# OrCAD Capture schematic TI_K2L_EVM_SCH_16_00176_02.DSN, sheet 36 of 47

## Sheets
36 PAGE45 : K2L_POWER SECTION 4: size C; title: K2L CVVD, CVVD1, bypass caps, K2L 1v8, K2L 1v0 PLL, caps, filters
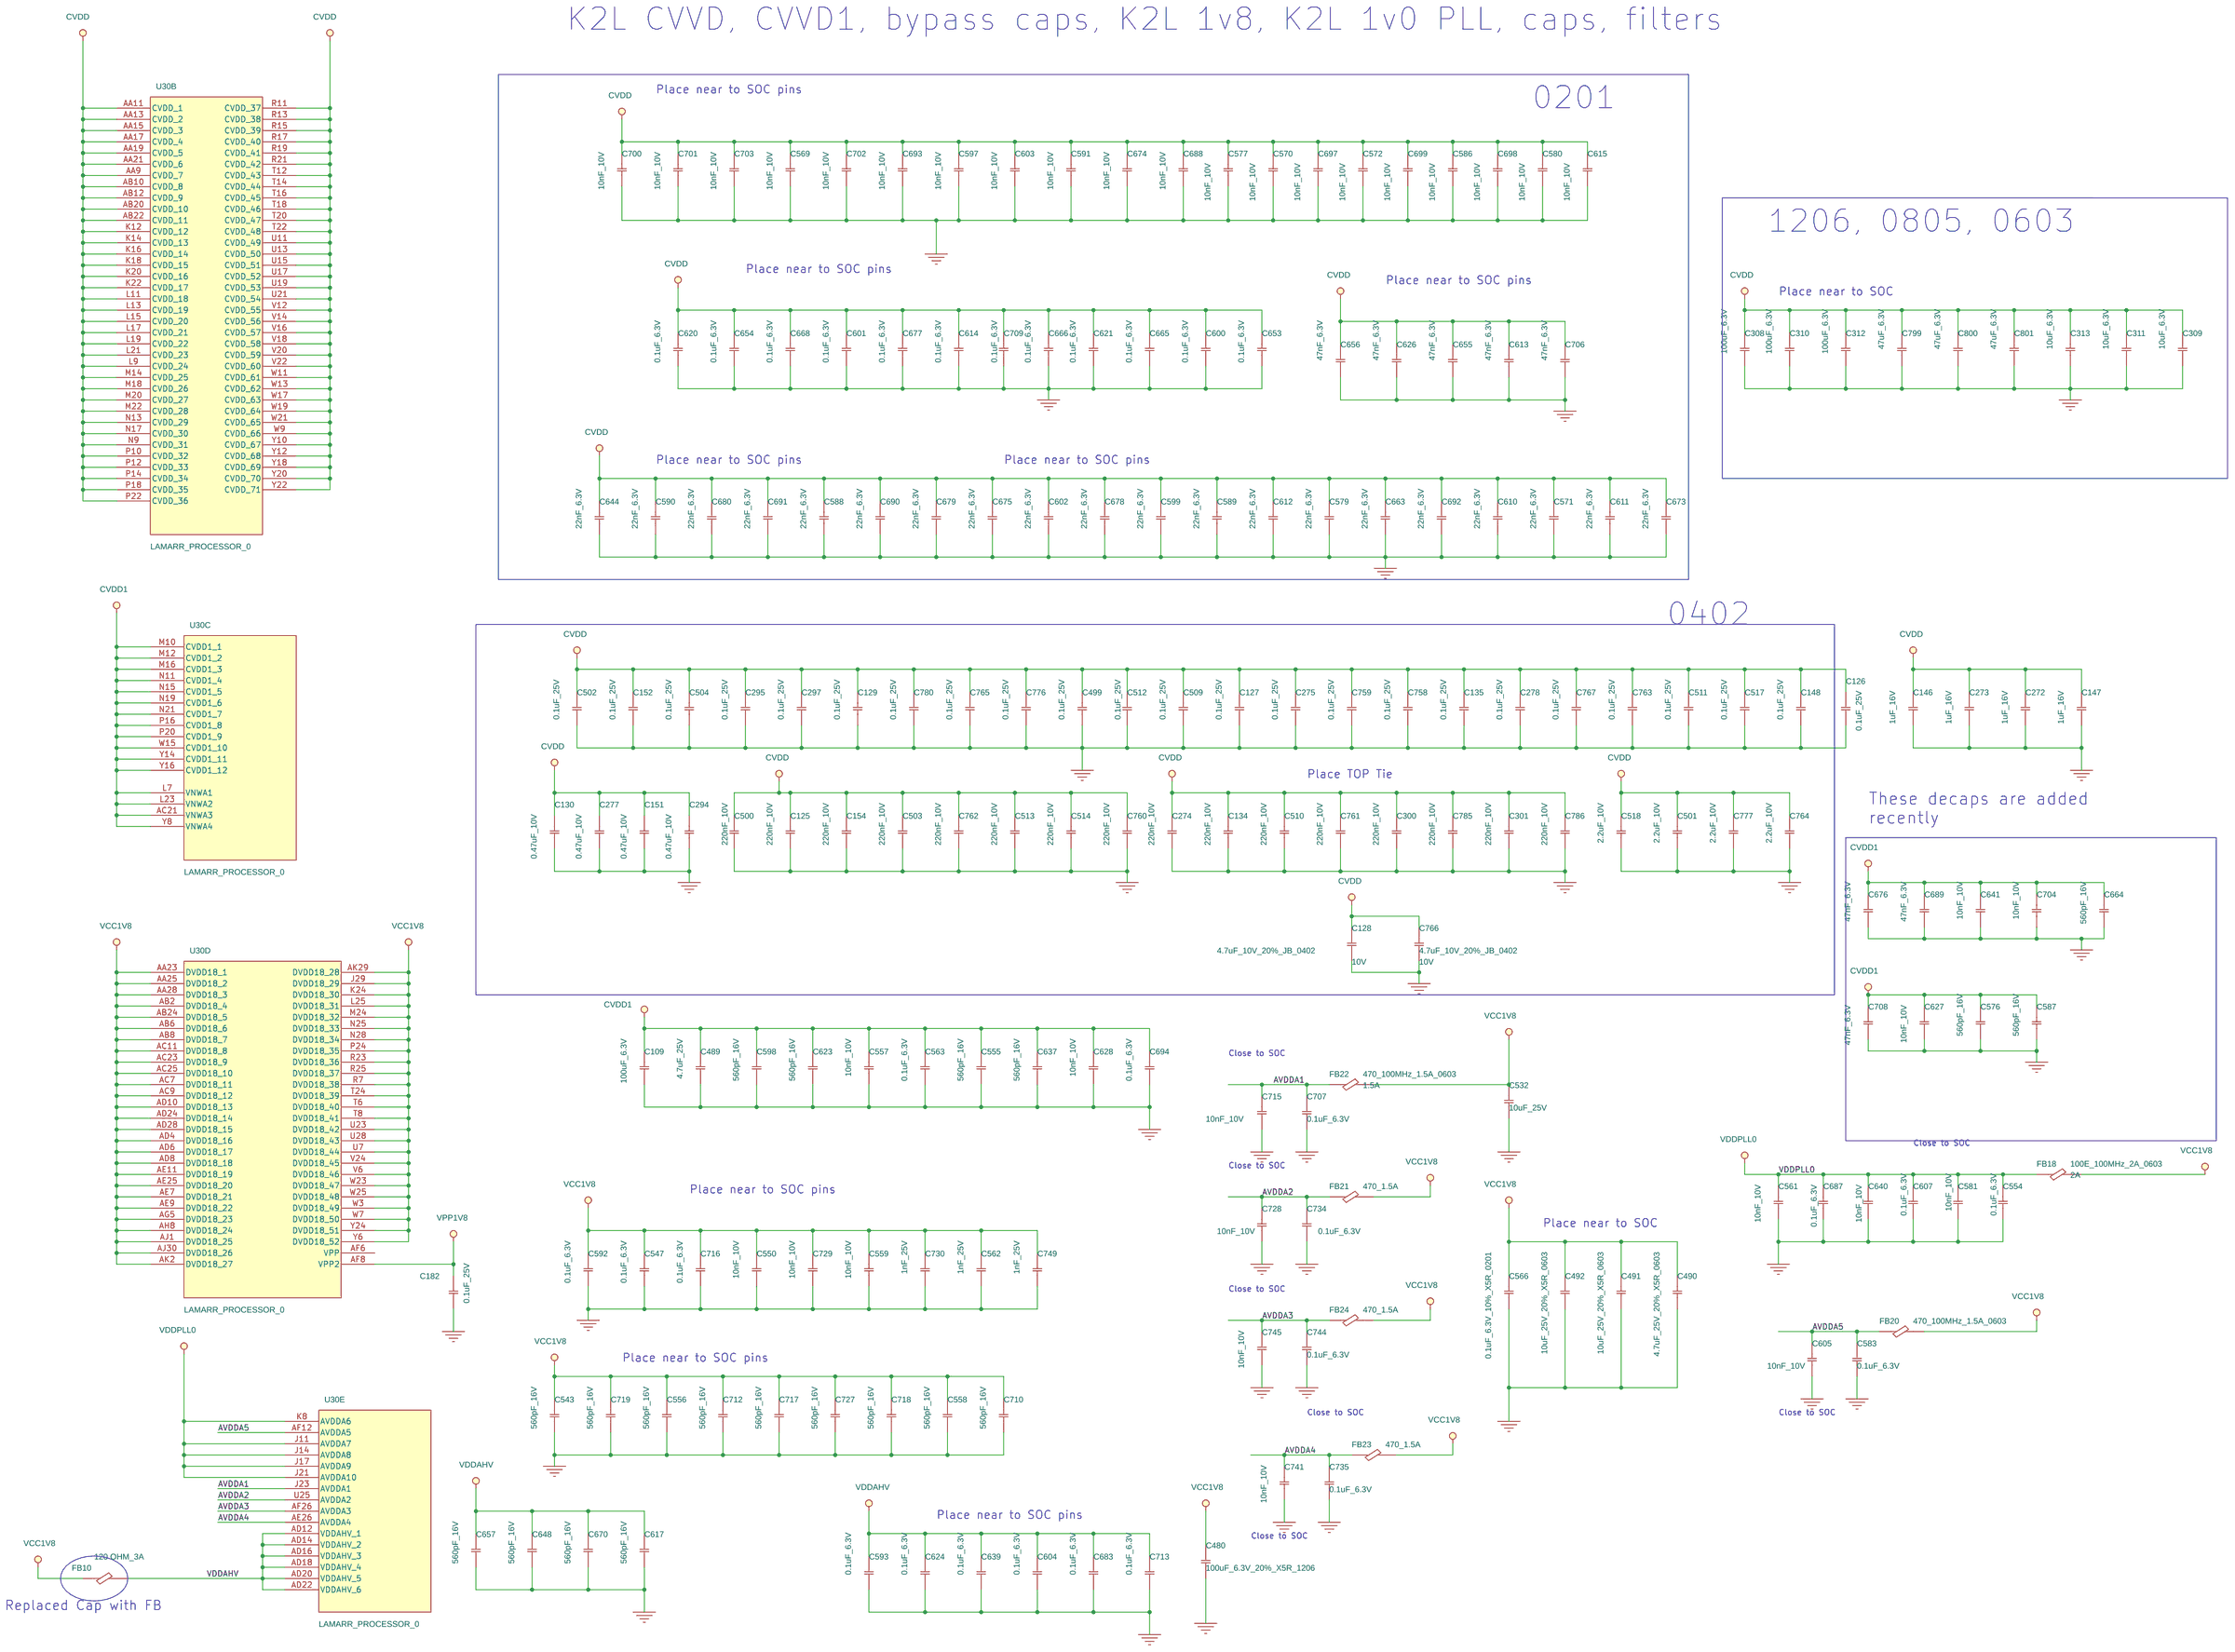
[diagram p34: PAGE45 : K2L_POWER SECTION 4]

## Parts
sheet PAGE24 : K2L_JTAG
U30  LAMARR_PROCESSOR_0  [SKTBGA_Z3566_SS900-RHFB-BGA080]  (sections A,B,C,D,E,F,G,H,I,J,K,L,M,N,O,P,Q,R,S,T,U)
sheet PAGE45 : K2L_POWER SECTION 4
C109  100uF_6.3V  [C1206-1]
C125  220nF_10V  [C0402]
C126  0.1uF_25V  [C0402]
C127  0.1uF_25V  [C0402]
C128  4.7uF_10V_20%_JB_0402  [C0402]
C129  0.1uF_25V  [C0402]
C130  0.47uF_10V  [C0402]
C134  220nF_10V  [C0402]
C135  0.1uF_25V  [C0402]
C146  1uF_16V  [C0402]
C147  1uF_16V  [C0402]
C148  0.1uF_25V  [C0402]
C151  0.47uF_10V  [C0402]
C152  0.1uF_25V  [C0402]
C154  220nF_10V  [C0402]
C182  0.1uF_25V  [C0402]
C272  1uF_16V  [C0402]
C273  1uF_16V  [C0402]
C274  220nF_10V  [C0402]
C275  0.1uF_25V  [C0402]
C277  0.47uF_10V  [C0402]
C278  0.1uF_25V  [C0402]
C294  0.47uF_10V  [C0402]
C295  0.1uF_25V  [C0402]
C297  0.1uF_25V  [C0402]
C300  220nF_10V  [C0402]
C301  220nF_10V  [C0402]
C308  100uF_6.3V  [C1206-1]
C309  10uF_6.3V  [C0603]
C310  100uF_6.3V  [C1206-1]
C311  10uF_6.3V  [C0603]
C312  100uF_6.3V  [C1206-1]
C313  10uF_6.3V  [C0603]
C480  100uF_6.3V_20%_X5R_1206  [C1206-1]
C489  4.7uF_25V  [C0603]
C490  4.7uF_25V_20%_X5R_0603  [C0603]
C491  10uF_25V_20%_X5R_0603  [C0603]
C492  10uF_25V_20%_X5R_0603  [C0603]
C499  0.1uF_25V  [C0402]
C500  220nF_10V  [C0402]
C501  2.2uF_10V  [C0402]
C502  0.1uF_25V  [C0402]
C503  220nF_10V  [C0402]
C504  0.1uF_25V  [C0402]
C509  0.1uF_25V  [C0402]
C510  220nF_10V  [C0402]
C511  0.1uF_25V  [C0402]
C512  0.1uF_25V  [C0402]
C513  220nF_10V  [C0402]
C514  220nF_10V  [C0402]
C517  0.1uF_25V  [C0402]
C518  2.2uF_10V  [C0402]
C532  10uF_25V  [C0603]
C543  560pF_16V  [CC0201_IPC7351_EINF]
C547  0.1uF_6.3V  [CC0201_IPC7351_EINF]
C550  10nF_10V  [CC0201_IPC7351_EINF]
C554  0.1uF_6.3V  [CC0201_IPC7351_EINF]
C555  560pF_16V  [CC0201_IPC7351_EINF]
C556  560pF_16V  [CC0201_IPC7351_EINF]
C557  10nF_10V  [CC0201_IPC7351_EINF]
C558  560pF_16V  [CC0201_IPC7351_EINF]
C559  10nF_10V  [CC0201_IPC7351_EINF]
C561  10nF_10V  [CC0201_IPC7351_EINF]
C562  1nF_25V  [CC0201_IPC7351_EINF]
C563  0.1uF_6.3V  [CC0201_IPC7351_EINF]
C566  0.1uF_6.3V_10%_X5R_0201  [CC0201_IPC7351_EINF]
C569  10nF_10V  [CC0201_IPC7351_EINF]
C570  10nF_10V  [CC0201_IPC7351_EINF]
C571  22nF_6.3V  [CC0201_IPC7351_EINF]
C572  10nF_10V  [CC0201_IPC7351_EINF]
C576  560pF_16V  [CC0201_IPC7351_EINF]
C577  10nF_10V  [CC0201_IPC7351_EINF]
C579  22nF_6.3V  [CC0201_IPC7351_EINF]
C580  10nF_10V  [CC0201_IPC7351_EINF]
C581  10nF_10V  [CC0201_IPC7351_EINF]
C583  0.1uF_6.3V  [CC0201_IPC7351_EINF]
C586  10nF_10V  [CC0201_IPC7351_EINF]
C587  560pF_16V  [CC0201_IPC7351_EINF]
C588  22nF_6.3V  [CC0201_IPC7351_EINF]
C589  22nF_6.3V  [CC0201_IPC7351_EINF]
C590  22nF_6.3V  [CC0201_IPC7351_EINF]
C591  10nF_10V  [CC0201_IPC7351_EINF]
C592  0.1uF_6.3V  [CC0201_IPC7351_EINF]
C593  0.1uF_6.3V  [CC0201_IPC7351_EINF]
C597  10nF_10V  [CC0201_IPC7351_EINF]
C598  560pF_16V  [CC0201_IPC7351_EINF]
C599  22nF_6.3V  [CC0201_IPC7351_EINF]
C600  0.1uF_6.3V  [CC0201_IPC7351_EINF]
C601  0.1uF_6.3V  [CC0201_IPC7351_EINF]
C602  22nF_6.3V  [CC0201_IPC7351_EINF]
C603  10nF_10V  [CC0201_IPC7351_EINF]
C604  0.1uF_6.3V  [CC0201_IPC7351_EINF]
C605  10nF_10V  [CC0201_IPC7351_EINF]
C607  0.1uF_6.3V  [CC0201_IPC7351_EINF]
C610  22nF_6.3V  [CC0201_IPC7351_EINF]
C611  22nF_6.3V  [CC0201_IPC7351_EINF]
C612  22nF_6.3V  [CC0201_IPC7351_EINF]
C613  47nF_6.3V  [CC0201_IPC7351_EINF]
C614  0.1uF_6.3V  [CC0201_IPC7351_EINF]
C615  10nF_10V  [CC0201_IPC7351_EINF]
C617  560pF_16V  [CC0201_IPC7351_EINF]
C620  0.1uF_6.3V  [CC0201_IPC7351_EINF]
C621  0.1uF_6.3V  [CC0201_IPC7351_EINF]
C623  560pF_16V  [CC0201_IPC7351_EINF]
C624  0.1uF_6.3V  [CC0201_IPC7351_EINF]
C626  47nF_6.3V  [CC0201_IPC7351_EINF]
C627  10nF_10V  [CC0201_IPC7351_EINF]
C628  10nF_10V  [CC0201_IPC7351_EINF]
C637  560pF_16V  [CC0201_IPC7351_EINF]
C639  0.1uF_6.3V  [CC0201_IPC7351_EINF]
C640  10nF_10V  [CC0201_IPC7351_EINF]
C641  10nF_10V  [CC0201_IPC7351_EINF]
C644  22nF_6.3V  [CC0201_IPC7351_EINF]
C648  560pF_16V  [CC0201_IPC7351_EINF]
C653  0.1uF_6.3V  [CC0201_IPC7351_EINF]
C654  0.1uF_6.3V  [CC0201_IPC7351_EINF]
C655  47nF_6.3V  [CC0201_IPC7351_EINF]
C656  47nF_6.3V  [CC0201_IPC7351_EINF]
C657  560pF_16V  [CC0201_IPC7351_EINF]
C663  22nF_6.3V  [CC0201_IPC7351_EINF]
C664  560pF_16V  [CC0201_IPC7351_EINF]
C665  0.1uF_6.3V  [CC0201_IPC7351_EINF]
C666  0.1uF_6.3V  [CC0201_IPC7351_EINF]
C668  0.1uF_6.3V  [CC0201_IPC7351_EINF]
C670  560pF_16V  [CC0201_IPC7351_EINF]
C673  22nF_6.3V  [CC0201_IPC7351_EINF]
C674  10nF_10V  [CC0201_IPC7351_EINF]
C675  22nF_6.3V  [CC0201_IPC7351_EINF]
C676  47nF_6.3V  [CC0201_IPC7351_EINF]
C677  0.1uF_6.3V  [CC0201_IPC7351_EINF]
C678  22nF_6.3V  [CC0201_IPC7351_EINF]
C679  22nF_6.3V  [CC0201_IPC7351_EINF]
C680  22nF_6.3V  [CC0201_IPC7351_EINF]
C683  0.1uF_6.3V  [CC0201_IPC7351_EINF]
C687  0.1uF_6.3V  [CC0201_IPC7351_EINF]
C688  10nF_10V  [CC0201_IPC7351_EINF]
C689  47nF_6.3V  [CC0201_IPC7351_EINF]
C690  22nF_6.3V  [CC0201_IPC7351_EINF]
C691  22nF_6.3V  [CC0201_IPC7351_EINF]
C692  22nF_6.3V  [CC0201_IPC7351_EINF]
C693  10nF_10V  [CC0201_IPC7351_EINF]
C694  0.1uF_6.3V  [CC0201_IPC7351_EINF]
C697  10nF_10V  [CC0201_IPC7351_EINF]
C698  10nF_10V  [CC0201_IPC7351_EINF]
C699  10nF_10V  [CC0201_IPC7351_EINF]
C700  10nF_10V  [CC0201_IPC7351_EINF]
C701  10nF_10V  [CC0201_IPC7351_EINF]
C702  10nF_10V  [CC0201_IPC7351_EINF]
C703  10nF_10V  [CC0201_IPC7351_EINF]
C704  10nF_10V  [CC0201_IPC7351_EINF]
C706  47nF_6.3V  [CC0201_IPC7351_EINF]
C707  0.1uF_6.3V  [CC0201_IPC7351_EINF]
C708  47nF_6.3V  [CC0201_IPC7351_EINF]
C709  0.1uF_6.3V  [CC0201_IPC7351_EINF]
C710  560pF_16V  [CC0201_IPC7351_EINF]
C712  560pF_16V  [CC0201_IPC7351_EINF]
C713  0.1uF_6.3V  [CC0201_IPC7351_EINF]
C715  10nF_10V  [CC0201_IPC7351_EINF]
C716  0.1uF_6.3V  [CC0201_IPC7351_EINF]
C717  560pF_16V  [CC0201_IPC7351_EINF]
C718  560pF_16V  [CC0201_IPC7351_EINF]
C719  560pF_16V  [CC0201_IPC7351_EINF]
C727  560pF_16V  [CC0201_IPC7351_EINF]
C728  10nF_10V  [CC0201_IPC7351_EINF]
C729  10nF_10V  [CC0201_IPC7351_EINF]
C730  1nF_25V  [CC0201_IPC7351_EINF]
C734  0.1uF_6.3V  [CC0201_IPC7351_EINF]
C735  0.1uF_6.3V  [CC0201_IPC7351_EINF]
C741  10nF_10V  [CC0201_IPC7351_EINF]
C744  0.1uF_6.3V  [CC0201_IPC7351_EINF]
C745  10nF_10V  [CC0201_IPC7351_EINF]
C749  1nF_25V  [CC0201_IPC7351_EINF]
C758  0.1uF_25V  [C0402]
C759  0.1uF_25V  [C0402]
C760  220nF_10V  [C0402]
C761  220nF_10V  [C0402]
C762  220nF_10V  [C0402]
C763  0.1uF_25V  [C0402]
C764  2.2uF_10V  [C0402]
C765  0.1uF_25V  [C0402]
C766  4.7uF_10V_20%_JB_0402  [C0402]
C767  0.1uF_25V  [C0402]
C776  0.1uF_25V  [C0402]
C777  2.2uF_10V  [C0402]
C780  0.1uF_25V  [C0402]
C785  220nF_10V  [C0402]
C786  220nF_10V  [C0402]
C799  47uF_6.3V  [C0805]
C800  47uF_6.3V  [C0805]
C801  47uF_6.3V  [C0805]
FB10  120 OHM_3A  [L0603]
FB18  100E_100MHz_2A_0603  [L0603]
FB20  470_100MHz_1.5A_0603  [L0603]
FB21  470_1.5A  [L0603]
FB22  470_100MHz_1.5A_0603  [L0603]
FB23  470_1.5A  [L0603]
FB24  470_1.5A  [L0603]

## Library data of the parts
U30 = LAMARR_PROCESSOR_7: LAMARR-SoC 900BGA 4DSP + 2ARM; Color: Default; Distributor_name: TBD; Distributor_part_number: TBD; EIC Part#: TBD; Location X-Coordinate: 0; Location Y-Coordinate: 0; Manufacture: TI; Manufacture Part Number: TCI6630K2L; Manufacture(English): TI; Manufacture_Part_Number: TCI6630K2L; Manufacturer: TI; Manufacturer_Part_No: TCI6630K2L; Mfg: TI; Mfg Part#: TBD; Mfr_name: TI; Mfr_part_number: LAMARR-SoC; Price @ 1: TBD; Price @ 10K: TBD; Price @ 1K: TBD; Primitive: DEFAULT; SPLIT_INST: TRUE; SWAP_INFO: (S1+S2+S3+S4+S5+S6+S7+S8+S9+S10+S11+S12+S13+S14+S15+S16+S17+S18+S19+S20+S21); Vendor: TBD; Vendor_Part_No: TBD; eI Part#: TBD
C109 C480 = 11_C_0: CAP CER 100UF 6.3V 20% X5R 1206; Distributor_name: DIGIKEY; Distributor_part_number: 587-1453-1-ND; EIC Part#: 03_00380_04; Manufacture: Taiyo Yuden; Manufacture Part Number: JMK316BJ107ML-T; Manufacture(English): Taiyo Yuden; Manufacture_Part_Number: JMK316BJ107ML-T; Manufacturer: Taiyo Yuden; Manufacturer_Part_No: JMK316BJ107ML-T; Mfg: Taiyo Yuden; Mfg Part#: 03_00380_04; Mfr_name: Taiyo Yuden; Mfr_part_number: JMK316BJ107ML-T; Oper. Temp. Range: -55C to 85C; Package: 1206; Price @ 1: 1.80000; Price @ 10K: 0.30450; Price @ 1K: 0.43050; ProcessType: SMT; RoHS: Yes; Tolerance: 20%; Vendor: DIGIKEY; Vendor Part#: 587-1963-1-ND; Vendor_Part_No: 587-1453-1-ND; Voltage: 6.3V; eI Part#: 03_00380_04
C125 C134 C154 C274 C500 C503 C510 C761 = Cap_Ceramic: CAP CER 0.22UF 10V 10% X5R 0402; Alt Mfg: Taiyo Yuden; Alt Mfg Part#: TMK105BJ104KV-F; Distributor_name: DIGIKEY; Distributor_part_number: 445-4985-1-ND; EIC Part#: TBD; MOUNTED: <MOUNTED>; Manufacture: TDK Corporation; Manufacture Part Number: C1005X5R1A224K050BC; Manufacture(English): TDK Corporation; Manufacturer: TDK Corporation; Manufacturer_Part_No: C1005X5R1A224K050BC; Mfg: TDK Corporation; Mfg Part#: TBD; Mfr_name: TDK Corporation; Mfr_part_number: C1005X5R1A224K050BC; Oper. Temp. Range: -55°C ~ 85°C; Package: 0402; ProcessType: SMT; RoHS: Yes; Tolerance: 10%; Vendor: DIGIKEY; Vendor Part#: 445-4985-1-ND; Vendor_Part_No: 445-4985-1-ND; Voltage: 10V; eI Part#: TBD
C126 C127 C129 C135 C148 C152 C275 C278 C295 C297 C499 C502 C504 C509 C511 C512 C517 C758 C759 C763 C765 C767 C776 C780 = Cap_Ceramic: CAP CER 0.1UF 25V 10% X5R 0402; Alt Mfg: Taiyo Yuden; Distributor_name: DIGIKEY; Distributor_part_number: 445-4964-1-ND; EIC Part#: 03_00470_02; MOUNTED: <MOUNTED>; Manufacture: TDK Corporation; Manufacture Part Number: C1005X5R1E104K050BC; Manufacture(English): TDK Corporation; Manufacturer: TDK Corporation; Manufacturer_Part_No: C1005X5R1E104K050BC; Mfg: TDK Corporation; Mfg Part#: 03_00470_02; Mfr_name: TDK Corporation; Mfr_part_number: C1005X5R1E104K050BC; Oper. Temp. Range: -55°C ~ 85°C; Package: 0402; ProcessType: SMT; RoHS: Yes; Tolerance: 10%; Vendor: DIGIKEY; Vendor Part#: 445-4964-1-ND; Vendor_Part_No: 445-4964-1-ND; eI Part#: 03_00470_02
C128 = Cap_Ceramic: CAP CER 4.7UF 10V 20% JB 0402; Characteristic: <Characteristic>; Distributor_name: DIGIKEY; Distributor_part_number: 445-10915-1-ND; EIC Part#: 03_00592_01; Manufacture: TDK Corporation; Manufacture Part Number: C1005JB1A475M050BC; Manufacture(English): TDK Corporation; Manufacturer: TDK Corporation; Manufacturer_Part_No: C1005JB1A475M050BC; Mfg: TDK Corporation; Mfg Part#: 03_00592_01; Mfr_name: TDK Corporation; Mfr_part_number: C1005JB1A475M050BC; Oper. Temp. Range: -55C to 85C; Package: 0603; ProcessType: SMT; RoHS: Yes; Tolerance: 10%; Vendor: DIGIKEY; Vendor Part#: 445-10915-1-ND; Vendor_Part_No: 445-10915-1-ND; Voltage: 10V; eI Part#: 03_00592_01
C130 C151 C294 = Cap_Ceramic: CAP CER 0.47UF 10V 10% X5R 0402; Characteristic: <Characteristic>; Distributor_name: DIGIKEY; Distributor_part_number: 445-4989-1-ND; EIC Part#: 03_00468_02; Manufacture: TDK Corporation; Manufacture Part Number: C1005X5R1A474K050BB; Manufacture(English): TDK Corporation; Manufacturer: TDK Corporation; Manufacturer_Part_No: C1005X5R1A474K050BB; Mfg: TDK Corporation; Mfg Part#: 03_00468_02; Mfr_name: TDK Corporation; Mfr_part_number: C1005X5R1A474K050BB; Oper. Temp. Range: -55C to 85C; Package: 0402; ProcessType: SMT; RoHS: Yes; Tolerance: 10%; Vendor: DIGIKEY; Vendor Part#: 445-4989-1-ND; Vendor_Part_No: 445-4989-1-ND; Voltage: 10V; eI Part#: 03_00468_02
C146 C147 C272 C273 = Cap_Ceramic: CAP CER 1UF 16V 10% X5R 0402; Characteristic: <Characteristic>; Distributor_name: DIGIKEY; Distributor_part_number: 445-4978-1-ND; EIC Part#: 03_00355_04; Manufacture: TDK Corporation; Manufacture Part Number: C1005X5R1C105K050BC; Manufacture(English): TDK Corporation; Manufacture_Part_Number: C1005X5R1C105K050BC; Manufacturer: TDK Corporation; Manufacturer_Part_No: C1005X5R1C105K050BC; Mfg: TDK Corporation; Mfg Part#: C1005X5R1C105K050BC; Mfr_name: TDK Corporation; Mfr_part_number: C1005X5R1C105K050BC; Oper. Temp. Range: -55C to 85C; Package: 0402; ProcessType: SMT; RoHS: Yes; Tolerance: 10%; Vendor: DIGIKEY; Vendor Part#: 445-4978-1-ND; Vendor_Part_No: 445-4978-1-ND; Voltage: 16V; eI Part#: 03_00355_04
C182 = 11_C_0: CAP CER 0.1UF 25V 10% X5R 0402; Alt Mfg: Taiyo Yuden; Distributor_name: DIGIKEY; Distributor_part_number: 445-4964-1-ND; EIC Part#: 03_00470_02; Manufacture: TDK Corporation; Manufacture Part Number: C1005X5R1E104K050BC; Manufacture(English): TDK Corporation; Manufacture_Part_Number: GRM155R61E104KA87D; Manufacturer: TDK Corporation; Manufacturer_Part_No: C1005X5R1E104K050BC; Mfg: Murata Electronics North America; Mfg Part#: 03_00470_02; Mfr_name: TDK Corporation; Mfr_part_number: C1005X5R1E104K050BC; Oper. Temp. Range: -55°C ~ 85°C; Package: 0402; Price @ 1: 0.10000; Price @ 1K: 0.00960; ProcessType: SMT; RoHS: Yes; Tolerance: 10%; Vendor: DIGIKEY; Vendor Part#: 445-4964-1-ND; Vendor_Part_No: 445-4964-1-ND; eI Part#: 03_00470_02
C277 = Cap_Ceramic: CAP CER 0.47UF 10V 10% X5R 0402; Distributor_name: DIGIKEY; Distributor_part_number: 445-4989-1-ND; EIC Part#: 03_00468_02; Manufacture: TDK Corporation; Manufacture Part Number: C1005X5R1A474K050BB; Manufacture(English): TDK Corporation; Manufacturer: TDK Corporation; Manufacturer_Part_No: C1005X5R1A474K050BB; Mfg: TDK Corporation; Mfg Part#: 03_00468_02; Mfr_name: TDK Corporation; Mfr_part_number: C1005X5R1A474K050BB; Oper. Temp. Range: -55C to 125C; Package: 0402; ProcessType: SMT; RoHS: Yes; Tolerance: 10%; Vendor: DIGIKEY; Vendor Part#: 445-4989-1-ND; Vendor_Part_No: 445-4989-1-ND; Voltage: 10V; eI Part#: 03_00468_02
C300 C301 C513 C514 C760 C762 C785 C786 = Cap_Ceramic: CAP CER 0.22UF 10V 10% X5R 0402; Distributor_name: DIGIKEY; Distributor_part_number: 445-4985-1-ND; EIC Part#: TBD; MOUNTED: <MOUNTED>; Manufacture: TDK Corporation; Manufacture Part Number: C1005X5R1A224K050BC; Manufacture(English): TDK Corporation; Manufacturer: TDK Corporation; Manufacturer_Part_No: C1005X5R1A224K050BC; Mfg: TDK Corporation; Mfg Part#: TBD; Mfr_name: TDK Corporation; Mfr_part_number: C1005X5R1A224K050BC; Oper. Temp. Range: -55°C ~ 85°C; Package: 0402; ProcessType: SMT; RoHS: Yes; Tolerance: 10%; Vendor: DIGIKEY; Vendor Part#: 445-4985-1-ND; Vendor_Part_No: 445-4985-1-ND; Voltage: 10V; eI Part#: TBD
C308 C310 C312 = Cap_Ceramic: CAP CER 100UF 6.3V 20% X5R 1206; Distributor_name: DIGIKEY; Distributor_part_number: 587-1453-1-ND; EIC Part#: 03_00380_04; Manufacture: Taiyo Yuden; Manufacture Part Number: JMK316BJ107ML-T; Manufacture(English): Taiyo Yuden; Manufacturer: Taiyo Yuden; Manufacturer_Part_No: JMK316BJ107ML-T; Mfg: Taiyo Yuden; Mfg Part#: 03_00380_04; Mfr_name: Taiyo Yuden; Mfr_part_number: JMK316BJ107ML-T; Oper. Temp. Range: -55C to 85C; Package: 1206; ProcessType: SMT; RoHS: Yes; Tolerance: 20%; Vendor: DIGIKEY; Vendor Part#: 587-1963-1-ND; Vendor_Part_No: 587-1453-1-ND; Voltage: 6.3V; eI Part#: 03_00380_04
C309 C311 C313 = Cap_Ceramic: CAP CER 10UF 6.3V 20% X5R 0603; Characteristic: <Characteristic>; Distributor_name: DIGIKEY; Distributor_part_number: 587-3383-1-ND; EIC Part#: 03_00605_01; Manufacture: Taiyo Yuden; Manufacture Part Number: JMK107ABJ106MAHT; Manufacture(English): Taiyo Yuden; Manufacture_Part_Number: JMK107ABJ106MAHT; Manufacturer: Taiyo Yuden; Manufacturer_Part_No: JMK107ABJ106MAHT; Mfg: Taiyo Yuden; Mfg Part#: JMK107ABJ106MAHT; Mfr_name: Taiyo Yuden; Mfr_part_number: JMK107ABJ106MAHT; Oper. Temp. Range: -55C to 85C; Package: 0603; Price @ 10K: 0.06105; ProcessType: SMT; RoHS: Yes; Tolerance: 20%; Vendor: DIGIKEY; Vendor Part#: 587-3383-1-ND; Vendor_Part_No: 587-3383-1-ND; Voltage: 25V; eI Part#: 03_00605_01
C489 = 11_C_12: CAP CER 4.7UF 25V 20% X5R 0603; Characteristic: <Characteristic>; Distributor_name: DIGIKEY; Distributor_part_number: 1276-1903-2-ND; EIC Part#: 03_00592_01; Manufacture: Samsung; Manufacture Part Number: CL10A475MA8NQNC; Manufacture(English): Samsung; Manufacture_Part_Number: CL10A475MA8NQNC; Manufacturer: Samsung; Manufacturer_Part_No: CL10A475MA8NQNC; Mfg: Samsung; Mfg Part#: CL10A475MA8NQNC; Mfr_name: Samsung; Mfr_part_number: CL10A475MA8NQNC; Oper. Temp. Range: -55C to 85C; Package: 0603; Price @ 1: 0.16000; Price @ 10K: 0.02322; Price @ 1K: 0.02970; ProcessType: SMT; RoHS: Yes; Tolerance: 10%; Vendor: DIGIKEY; Vendor Part#: 1276-1903-2-ND; Vendor_Part_No: 1276-1903-2-ND; Voltage: 6.3V; eI Part#: 03_00592_01
C490 = 11_C_12: CAP CER 4.7UF 25V 20% X5R 0603; Characteristic: <Characteristic>; Distributor_name: DIGIKEY; Distributor_part_number: 1276-1903-2-ND; EIC Part#: 03_00592_01; Manufacture: Samsung; Manufacture Part Number: CL10A475MA8NQNC; Manufacture(English): Samsung; Manufacture_Part_Number: CL10A475MA8NQNC; Manufacturer: Samsung; Manufacturer_Part_No: CL10A475MA8NQNC; Mfg: Samsung; Mfg Part#: CL10A475MA8NQNC; Mfr_name: Samsung; Mfr_part_number: CL10A475MA8NQNC; Oper. Temp. Range: -55C to 85C; Package: 0603; Price @ 1: 0.30000; Price @ 10K: 0.05717; Price @ 1K: 0.07262; ProcessType: SMT; RoHS: Yes; Tolerance: 10%; Vendor: DIGIKEY; Vendor Part#: 1276-1903-2-ND; Vendor_Part_No: 1276-1903-2-ND; Voltage: 25V; eI Part#: 03_00592_01
C491 C492 C532 = 11_C_12: CAP CER 10UF 25V 20% X5R 0603; Characteristic: <Characteristic>; Distributor_name: DIGIKEY; Distributor_part_number: 445-9015-1-ND; EIC Part#: 03_00609_01; Manufacture: TDK Corporation; Manufacture Part Number: C1608X5R1E106M080AC; Manufacture(English): TDK Corporation; Manufacture_Part_Number: C1608X5R1E106M080AC; Manufacturer: TDK Corporation; Manufacturer_Part_No: C1608X5R1E106M080AC; Mfg: TDK Corporation; Mfg Part#: C1608X5R1E106M080AC; Mfr_name: TDK Corporation; Mfr_part_number: C1608X5R1E106M080AC; Oper. Temp. Range: -55C to 85C; Package: 0603; Price @ 1: 0.60000; Price @ 10K: 0.19125; Price @ 1K: 0.19125; ProcessType: SMT; RoHS: Yes; Tolerance: 20%; Vendor: DIGIKEY; Vendor Part#: TDK Corporation; Vendor_Part_No: 445-9015-1-ND; Voltage: 25V; eI Part#: 03_00609_01
C501 C518 C764 C777 = Cap_Ceramic: CAP CER 2.2UF 10V 10% X5R 0402; Characteristic: <Characteristic>; Distributor_name: DIGIKEY; Distributor_part_number: 445-7392-1-ND; EIC Part#: 03_00055_05; Manufacture: TDK Corporation; Manufacture Part Number: C1005X5R1A225K050BC; Manufacture(English): TDK Corporation; Manufacture_Part_Number: C1005X5R1A225K050BC; Manufacturer: TDK Corporation; Manufacturer_Part_No: C1005X5R1A225K050BC; Mfg: TDK Corporation; Mfg Part#: C1005X5R1A225K050BC; Mfr_name: TDK Corporation; Mfr_part_number: C1005X5R1A225K050BC; Oper. Temp. Range: -55C to 105C; Package: 0402; ProcessType: SMT; RoHS: Yes; Tolerance: 10%; Vendor: DIGIKEY; Vendor Part#: 445-7392-1-ND; Vendor_Part_No: 445-7392-1-ND; Voltage: 10V; eI Part#: 03_00055_05
C543 C555 C556 C558 C576 C587 C598 C617 C623 C637 C648 C657 C664 C670 C710 C712 C717-C719 C727 = 11_C_12: CAP CER 560PF 16V 10% X7R 0201; Avalue_Part_Number: E1127556100H; Characteristic: 50V; Distributor_name: DIGIKEY; Distributor_part_number: 1276-1357-1-ND; EIC Part#: 03_00590_01; Manufacture: Samsung; Manufacture Part Number: CL03B561KO3NNNC; Manufacture(English): Samsung; Manufacture_Part_Number: CL03B561KO3NNNC; Manufacturer: Samsung; Manufacturer_Part_No: CL03B561KO3NNNC; Mfg: Samsung; Mfg Part#: 03_00590_01; Mfr_name: Samsung; Mfr_part_number: CL03B561KO3NNNC; Oper. Temp. Range: -55°C ~ 125°C; Package: 0201; Price @ 1: 0.10000; Price @ 10K: 0.00441; Price @ 1K: 0.00630; ProcessType: SMT; RoHS: Yes; Tolerance: 10%; Vendor: DIGIKEY; Vendor Part#: 1276-1357-1-ND; Vendor_Part_No: 1276-1357-1-ND; Voltage: 16V; eI Part#: 03_00590_01
C547 C554 C563 C566 C583 C592 C593 C604 C607 C624 C639 C683 C687 C694 C707 C713 C716 C734 C735 C744 = 11_C_12: CAP CER 0.1UF 6.3V 10% X5R 0201; Alt Mfg: Taiyo Yuden; Alt Mfg Part#: TMK105BJ104KV-F; Characteristic: <Characteristic>; Distributor_name: DIGIKEY; Distributor_part_number: 445-1796-1-ND; EIC Part#: 03_00583_01; Manufacture: TDK Corporation; Manufacture Part Number: C0603X5R0J104K030BC; Manufacture(English): TDK Corporation; Manufacture_Part_Number: C0603X5R0J104K030BC; Manufacturer: TDK Corporation; Manufacturer_Part_No: C0603X5R0J104K030BC; Mfg: TDK Corporation; Mfg Part#: 03_00583_01; Mfr_name: TDK Corporation; Mfr_part_number: C0603X5R0J104K030BC; Oper. Temp. Range: -55°C ~ 85°C; Package: 0201; Price @ 1: 0.10000; Price @ 10K: 0.00675; Price @ 1K: 0.00810; ProcessType: SMT; RoHS: Yes; Tolerance: 10%; Vendor: DIGIKEY; Vendor Part#: 445-1796-2-ND; Vendor_Part_No: 445-1796-1-ND; Voltage: 6.3V; eI Part#: 03_00583_01
C550 C559 C561 C581 C605 C640 C715 C728 C729 C741 C745 = 11_C_0: CAP CER 10000PF 10V 20% X5R 0201; Alt Mfg: Murata; Alt Mfg Part#: GRM155R71C103KA01D; Distributor_name: DIGIKEY; Distributor_part_number: 445-4702-1-ND; EIC Part#: 03_00551_02; Manufacture: TDK Corporation; Manufacture Part Number: C0603X5R1A103M030BA; Manufacture(English): TDK Corporation; Manufacture_Part_Number: C0603X5R1A103M030BA; Manufacturer: TDK Corporation; Manufacturer_Part_No: C0603X5R1A103M030BA; Mfg: TDK Corporation; Mfg Part#: 03_00551_02; Mfr_name: TDK Corporation; Mfr_part_number: C0603X5R1A103M030BA; Oper. Temp. Range: -55C to 125C; Package: 0201; Price @ 1: 0.10000; Price @ 10K: 0.00500; Price @ 1K: 0.00600; ProcessType: SMT; RoHS: Yes; Tolerance: 10%; Vendor: DIGIKEY; Vendor Part#: 445-4702-1-ND; Vendor_Part_No: 445-4702-1-ND; Voltage: 6.3V; eI Part#: 03_00551_02
C557 C627 C628 C641 C704 = 11_C_0: CAP CER 10000PF 10V 20% X5R 0201; Alt Mfg: Murata; Alt Mfg Part#: GRM155R71C103KA01D; Distributor_name: DIGIKEY; Distributor_part_number: 445-4702-1-ND; EIC Part#: 03_00551_02; Manufacture: TDK Corporation; Manufacture Part Number: C0603X5R1A103M030BA; Manufacture(English): TDK Corporation; Manufacture_Part_Number: C0603X5R1A103M030BA; Manufacturer: TDK Corporation; Manufacturer_Part_No: C0603X5R1A103M030BA; Mfg: TDK Corporation; Mfg Part#: 03_00551_02; Mfr_name: TDK Corporation; Mfr_part_number: C0603X5R1A103M030BA; Oper. Temp. Range: -55C to 125C; Package: 0402; Price @ 1: 0.10000; Price @ 10K: 0.00500; Price @ 1K: 0.00600; ProcessType: SMT; RoHS: Yes; Tolerance: 10%; Vendor: DIGIKEY; Vendor Part#: 445-4702-1-ND; Vendor_Part_No: 445-4702-1-ND; Voltage: 6.3V; eI Part#: 03_00551_02
C562 C730 C749 = 11_C_12: CAP CER 1000PF 25V 10% X7R 0201; Advansus_Part_Number: 11G232110214030; Characteristic: 50V; Distributor_name: DIGIKEY; Distributor_part_number: 445-7275-1-ND; EIC Part#: 03_00387_02; Manufacture: TDK Corporation; Manufacture Part Number: C0603X7R1E102K030BA; Manufacture(English): TDK Corporation; Manufacture_Part_Number: C0603X7R1E102K030BA; Manufacturer: TDK Corporation; Manufacturer_Part_No: C0603X7R1E102K030BA; Mfg: TDK Corporation; Mfg Part#: 03_00387_02; Mfr_name: TDK Corporation; Mfr_part_number: C0603X7R1E102K030BA; Oper. Temp. Range: -55°C ~ 125°C; Package: 0201; Price @ 1: 0.10000; Price @ 10K: 0.00500; Price @ 1K: 0.00600; ProcessType: SMT; RoHS: Yes; Tolerance: 10%; Vendor: DIGIKEY; Vendor Part#: 445-7275-2-ND; Vendor_Part_No: 445-7275-1-ND; Voltage: 25V; eI Part#: 03_00387_02
C569 C570 C572 C577 C580 C586 C591 C597 C603 C615 C674 C688 C693 C697-C703 = Cap_Ceramic: CAP CER 10000PF 10V 20% X5R 0201; Alt Mfg: Murata; Alt Mfg Part#: GRM155R71C103KA01D; Distributor_name: DIGIKEY; Distributor_part_number: 445-4702-1-ND; EIC Part#: 03_00551_02; Manufacture: TDK Corporation; Manufacture Part Number: C0603X5R1A103M030BA; Manufacture(English): TDK Corporation; Manufacture_Part_Number: C0603X5R1A103M030BA; Manufacturer: TDK Corporation; Manufacturer_Part_No: C0603X5R1A103M030BA; Mfg: TDK Corporation; Mfg Part#: 03_00551_02; Mfr_name: TDK Corporation; Mfr_part_number: C0603X5R1A103M030BA; Oper. Temp. Range: -55C to 125C; Package: 0201; ProcessType: SMT; RoHS: Yes; Tolerance: 10%; Vendor: DIGIKEY; Vendor Part#: 445-4702-1-ND; Vendor_Part_No: 445-4702-1-ND; eI Part#: 03_00551_02
C571 = Cap_Ceramic: CAP CER 0.022UF 6.3V 10% JB 0201; Alt Mfg: TBD; Distributor_name: DIGIKEY; Distributor_part_number: 445-10732-1-ND; EIC Part#: TBD; Manufacture: TDK Corporation; Manufacture Part Number: C0603JB0J223K030BC; Manufacture(English): TDK Corporation; Manufacture_Part_Number: TBD; Manufacturer: TDK Corporation; Manufacturer_Part_No: C0603JB0J223K030BC; Mfg: TDK Corporation; Mfg Part#: TBD; Mfr_name: TDK Corporation; Mfr_part_number: C0603JB0J223K030BC; Oper. Temp. Range: -55°C ~ 125°C; Package: 0201; Price @ 1: TBD; ProcessType: SMT; RoHS: Yes; Tolerance: 10%; Vendor: DIGIKEY; Vendor Part#: 445-10732-1-ND; Vendor_Part_No: 445-10732-1-ND; Voltage: 6.3V; eI Part#: TBD
C579 C589 C599 C602 C610-C612 C663 C673 C675 C678 C692 = Cap_Ceramic: CAP CER 0.022UF 6.3V 10% JB 0201; Distributor_name: DIGIKEY; Distributor_part_number: 445-10732-1-ND; EIC Part#: TBD; Manufacture: TDK Corporation; Manufacture Part Number: C0603JB0J223K030BC; Manufacture(English): TDK Corporation; Manufacture_Part_Number: TBD; Manufacturer: TDK Corporation; Manufacturer_Part_No: C0603JB0J223K030BC; Mfg: TDK Corporation; Mfg Part#: TBD; Mfr_name: TDK Corporation; Mfr_part_number: C0603JB0J223K030BC; Oper. Temp. Range: -55°C ~ 125°C; Package: 0201; ProcessType: SMT; RoHS: Yes; Tolerance: 10%; Vendor: DIGIKEY; Vendor Part#: 445-10732-1-ND; Vendor_Part_No: 445-10732-1-ND; Voltage: 6.3V; eI Part#: TBD
C588 C590 C644 C679 C680 C690 C691 = Cap_Ceramic: CAP CER 0.022UF 6.3V 10% JB 0201; Distributor_name: DIGIKEY; Distributor_part_number: 445-10732-1-ND; EIC Part#: TBD; Manufacture: TDK Corporation; Manufacture Part Number: C0603JB0J223K030BC; Manufacture(English): TDK Corporation; Manufacture_Part_Number: TBD; Manufacturer: TDK Corporation; Manufacturer_Part_No: C0603JB0J223K030BC; Mfg: TDK Corporation; Mfg Part#: TBD; Mfr_name: TDK Corporation; Mfr_part_number: C0603JB0J223K030BC; Oper. Temp. Range: -55C to 125C; Package: 0201; ProcessType: SMT; RoHS: Yes; Tolerance: 10%; Vendor: DIGIKEY; Vendor Part#: 445-10732-1-ND; Vendor_Part_No: 445-10732-1-ND; Voltage: 6.3V; eI Part#: TBD
C600 C601 C614 C620 C621 C653 C654 C665 C666 C668 C677 C709 = Cap_Ceramic: CAP CER 0.1UF 6.3V 10% X5R 0201; Alt Mfg: Taiyo Yuden; Alt Mfg Part#: TMK105BJ104KV-F; Characteristic: <Characteristic>; Distributor_name: DIGIKEY; Distributor_part_number: 445-1796-1-ND; EIC Part#: 03_00583_01; Manufacture: TDK Corporation; Manufacture Part Number: C0603X5R0J104K030BC; Manufacture(English): TDK Corporation; Manufacture_Part_Number: TBD; Manufacturer: TDK Corporation; Manufacturer_Part_No: C0603X5R0J104K030BC; Mfg: TDK Corporation; Mfg Part#: 03_00583_01; Mfr_name: TDK Corporation; Mfr_part_number: C0603X5R0J104K030BC; Oper. Temp. Range: -55°C ~ 85°C; Package: 0201; ProcessType: SMT; RoHS: Yes; Tolerance: 10%; Vendor: DIGIKEY; Vendor Part#: 445-1796-2-ND; Vendor_Part_No: 445-1796-1-ND; eI Part#: 03_00583_01
C613 C626 C655 C656 C706 = Cap_Ceramic: CAP CER 0.047UF 6.3V X5R 0201; Characteristic: 50V; Distributor_name: DIGIKEY; Distributor_part_number: 445-1795-1-ND; EIC Part#: 03_00584_01; Manufacture: TDK Corporation; Manufacture Part Number: C0603X5R0J473K030BC; Manufacture(English): TDK Corporation; Manufacture_Part_Number: C0603X5R0J473K030BC; Manufacturer: TDK Corporation; Manufacturer_Part_No: C0603X5R0J473K030BC; Mfg: TDK Corporation; Mfg Part#: 03_00584_01; Mfr_name: TDK Corporation; Mfr_part_number: C0603X5R0J473K030BC; Oper. Temp. Range: -55°C ~ 125°C; Package: 0201; Price @ 1: 0.10000; Price @ 10K: 0.00640; ProcessType: SMT; RoHS: Yes; Tolerance: 10%; Vendor: DIGIKEY; Vendor Part#: 445-1795-2-ND; Vendor_Part_No: 445-1795-1-ND; eI Part#: 03_00584_01
C676 C689 C708 = 11_C_12: CAP CER 0.047UF 6.3V X5R 0201; Avalue_Part_Number: E1127556100H; Characteristic: 50V; Distributor_name: DIGIKEY; Distributor_part_number: 445-1795-1-ND; EIC Part#: 03_00584_01; Manufacture: TDK Corporation; Manufacture Part Number: C0603X5R0J473K030BC; Manufacture(English): TDK Corporation; Manufacture_Part_Number: C0603X5R0J473K030BC; Manufacturer: TDK Corporation; Manufacturer_Part_No: C0603X5R0J473K030BC; Mfg: TDK Corporation; Mfg Part#: 03_00584_01; Mfr_name: TDK Corporation; Mfr_part_number: C0603X5R0J473K030BC; Oper. Temp. Range: -55°C ~ 125°C; Package: 0201; Price @ 1: 0.10000; Price @ 10K: 0.00640; Price @ 1K: 0.00960; ProcessType: SMT; RoHS: Yes; Tolerance: 10%; Vendor: DIGIKEY; Vendor Part#: 445-1795-2-ND; Vendor_Part_No: 445-1795-1-ND; Voltage: 6.3V; eI Part#: 03_00584_01
C766 = Cap_Ceramic: CAP CER 4.7UF 10V 20% JB 0402; Characteristic: <Characteristic>; Distributor_name: DIGIKEY; Distributor_part_number: 445-10915-1-ND; EIC Part#: 03_00592_01; Manufacture: TDK Corporation; Manufacture Part Number: C1005JB1A475M050BC; Manufacture(English): TDK Corporation; Manufacturer: TDK Corporation; Manufacturer_Part_No: C1005JB1A475M050BC; Mfg: TDK Corporation; Mfg Part#: 03_00592_01; Mfr_name: TDK Corporation; Mfr_part_number: C1005JB1A475M050BC; Oper. Temp. Range: -55C to 85C; Package: 0402; ProcessType: SMT; RoHS: Yes; Tolerance: 10%; Vendor: DIGIKEY; Vendor Part#: 445-10915-1-ND; Vendor_Part_No: 445-10915-1-ND; Voltage: 10V; eI Part#: 03_00592_01
C799-C801 = Cap_Ceramic: CAP CER 47UF 6.3V 20% X5R 0805; Distributor_name: DIGIKEY; Distributor_part_number: 587-1779-1-ND; EIC Part#: 03_00328_01; Manufacture: Taiyo Yuden; Manufacture Part Number: JMK212BJ476MG-T; Manufacture(English): Taiyo Yuden; Manufacturer: Taiyo Yuden; Manufacturer_Part_No: JMK212BJ476MG-T; Mfg: Taiyo Yuden; Mfg Part#: 03_00328_01; Mfr_name: Taiyo Yuden; Mfr_part_number: JMK212BJ476MG-T; Oper. Temp. Range: -55C to 105C; Package: 0805; ProcessType: SMT; RoHS: Yes; Tolerance: 20%; Vendor: DIGIKEY; Vendor Part#: 587-1779-1-ND; Vendor_Part_No: 587-1779-1-ND; Voltage: 6.3V; eI Part#: 03_00328_01
FB10 = 1212_BEAD_0: FILTER CHIP 120 OHM 3A 0603; Distributor_name: DIGIKEY; Distributor_part_number: 490-3996-1-ND; EIC Part#: 04_00405_01; Manufacture: Murata; Manufacture Part Number: BLM18SG121TN1D; Manufacture(English): Murata; Manufacture_Part_Number: BLM18SG121TN1D; Manufacturer: Murata; Manufacturer_Part_No: BLM18SG121TN1D; Mfg: Murata Electronics North America; Mfg Part#: 04_00405_01; Mfr_name: Murata; Mfr_part_number: BLM18SG121TN1D; Part_Number: 1212002506; Price @ 1: 0.14000; Price @ 10K: 0.03173; Price @ 1K: 0.03878; RoHS: Yes; Vendor: DIGIKEY; Vendor Part#: 490-3996-1-ND; Vendor_Part_No: 490-3996-1-ND; eI Part#: 04_00405_01
FB18 = 1212_BEAD_0: FERRITE CHIP 100 OHM 2A 0603; Characteristic: 2A; Distributor_name: DIGIKEY; EIC Part#: 04_00404_01; Manufacture: Murata; Manufacture Part Number: BLM18EG101TN1D; Manufacture(English): Murata; Manufacture_Part_Number: BLM18EG101TN1D; Manufacturer: Murata; Manufacturer_Part_No: BLM18EG101TN1D; Mfg: Murata Electronics North America; Mfg Part#: 04_00404_01; Mfr_name: Murata; Mfr_part_number: BLM18EG101TN1D; Package: 0603; Part_Number: 1212002966-01; Price @ 1: 0.23000; Price @ 10K: 0.06370; Price @ 1K: 0.07257; ProcessType: SMT; RoHS: Yes; Tolerance: 25%; Vendor: DIGIKEY; Vendor Part#: 490-5978-1-ND; eI Part#: 04_00404_01
FB20-FB24 = 1212_BEAD_0: FERRITE CHIP 470 OHM 1500MA 0603; Characteristic: 1.5A; Distributor_name: DIGIKEY; Distributor_part_number: 490-5257-1-ND; EIC Part#: 04_00281_01; Manufacture: Murata; Manufacture Part Number: BLM18KG471SN1D; Manufacture(English): Murata; Manufacture_Part_Number: BLM18KG471SN1D; Manufacturer: Murata; Manufacturer_Part_No: BLM18KG471SN1D; Mfg: Murata Electronics North America; Mfg Part#: 04_00281_01; Mfr_name: Murata; Mfr_part_number: BLM18KG471SN1D; Package: 0603; Price @ 1: 0.10000; Price @ 10K: 0.02304; Price @ 1K: 0.03010; ProcessType: SMT; RoHS: Yes; Tolerance: 25%; Vendor: DIGIKEY; Vendor Part#: 490-5257-1-ND; Vendor_Part_No: 490-5257-1-ND; eI Part#: 04_00281_01

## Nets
AVDDA1: C707.1 C715.1 FB22.1 U30.J23(AVDDA1)
AVDDA2: C728.1 C734.1 FB21.1 U30.U25(AVDDA2)
AVDDA3: C744.1 C745.1 FB24.1 U30.AF26(AVDDA3)
AVDDA4: C735.1 C741.1 FB23.1 U30.AE26(AVDDA4)
AVDDA5: C583.1 C605.1 FB20.1 U30.AF12(AVDDA5)
GND: C109.2 C125.1 C126.1 C127.1 C128.2 C129.1 C130.2 C134.1 C135.1 C146.2 C147.2 C148.1 C151.2 C152.1 C154.1 C182.2 C272.2 C273.2 C274.1 C275.1 C277.2 C278.1 C294.2 C295.1 C297.1 C300.1 C301.1 C308.2 C309.2 C310.2 C311.2 C312.2 C313.2 C480.2 C489.2 C490.2 C491.2 C492.2 C499.1 C500.1 C501.2 C502.1 C503.1 C504.1 C509.1 C510.1 C511.1 C512.1 C513.1 C514.1 C517.1 C518.2 C532.2 C543.2 C547.2 C550.2 C554.2 C555.2 C556.2 C557.2 C558.2 C559.2 C561.2 C562.2 C563.2 C566.2 C569.2 C570.2 C571.2 C572.2 C576.2 C577.2 C579.2 C580.2 C581.2 C583.2 C586.2 C587.2 C588.2 C589.2 C590.2 C591.2 C592.2 C593.2 C597.2 C598.2 C599.2 C600.2 C601.2 C602.2 C603.2 C604.2 C605.2 C607.2 C610.2 C611.2 C612.2 C613.2 C614.2 C615.2 C617.2 C620.2 C621.2 C623.2 C624.2 C626.2 C627.2 C628.2 C637.2 C639.2 C640.2 C641.2 C644.2 C648.2 C653.2 C654.2 C655.2 C656.2 C657.2 C663.2 C664.2 C665.2 C666.2 C668.2 C670.2 C673.2 C674.2 C675.2 C676.2 C677.2 C678.2 C679.2 C680.2 C683.2 C687.2 C688.2 C689.2 C690.2 C691.2 C692.2 C693.2 C694.2 C697.2 C698.2 C699.2 C700.2 C701.2 C702.2 C703.2 C704.2 C706.2 C707.2 C708.2 C709.2 C710.2 C712.2 C713.2 C715.2 C716.2 C717.2 C718.2 C719.2 C727.2 C728.2 C729.2 C730.2 C734.2 C735.2 C741.2 C744.2 C745.2 C749.2 C758.1 C759.1 C760.1 C761.1 C762.1 C763.1 C764.2 C765.1 C766.2 C767.1 C776.1 C777.2 C780.1 C785.1 C786.1 C799.2 C800.2 C801.2 ; also on sheet 1 2 3 4 5 6 8 10 11 12 13 14 15 16 17 18 19 20 21 22 24 25 26 27 28 29 33 34 35 37 40 41 42 43 45 46 47
VCC1V8: C480.1 C490.1 C491.1 C492.1 C532.1 C543.1 C547.1 C550.1 C556.1 C558.1 C559.1 C562.1 C566.1 C592.1 C710.1 C712.1 C716.1 C717.1 C718.1 C719.1 C727.1 C729.1 C730.1 C749.1 FB10.1 FB18.2 FB20.2 FB21.2 FB22.2 FB23.2 FB24.2 U30.AA23(DVDD18_1) U30.AA25(DVDD18_2) U30.AA28(DVDD18_3) U30.AB2(DVDD18_4) U30.AB6(DVDD18_6) U30.AB8(DVDD18_7) U30.AB24(DVDD18_5) U30.AC7(DVDD18_11) U30.AC9(DVDD18_12) U30.AC11(DVDD18_8) U30.AC23(DVDD18_9) U30.AC25(DVDD18_10) U30.AD4(DVDD18_16) U30.AD6(DVDD18_17) U30.AD8(DVDD18_18) U30.AD10(DVDD18_13) U30.AD24(DVDD18_14) U30.AD28(DVDD18_15) U30.AE7(DVDD18_21) U30.AE9(DVDD18_22) U30.AE11(DVDD18_19) U30.AE25(DVDD18_20) U30.AG5(DVDD18_23) U30.AH8(DVDD18_24) U30.AJ1(DVDD18_25) U30.AJ30(DVDD18_26) U30.AK2(DVDD18_27) U30.AK29(DVDD18_28) U30.J29(DVDD18_29) U30.K24(DVDD18_30) U30.L25(DVDD18_31) U30.M24(DVDD18_32) U30.N25(DVDD18_33) U30.N28(DVDD18_34) U30.P24(DVDD18_35) U30.R7(DVDD18_38) U30.R23(DVDD18_36) U30.R25(DVDD18_37) U30.T6(DVDD18_40) U30.T8(DVDD18_41) U30.T24(DVDD18_39) U30.U7(DVDD18_44) U30.U23(DVDD18_42) U30.U28(DVDD18_43) U30.V6(DVDD18_46) U30.V24(DVDD18_45) U30.W3(DVDD18_49) U30.W7(DVDD18_50) U30.W23(DVDD18_47) U30.W25(DVDD18_48) U30.Y6(DVDD18_52) U30.Y24(DVDD18_51) ; also on sheet 2 6 8 11 19 21 22 25 26 27 29 33 34 37 41
VDDAHV: C593.1 C604.1 C617.1 C624.1 C639.1 C648.1 C657.1 C670.1 C683.1 C713.1 FB10.2 U30.AD12(VDDAHV_1) U30.AD14(VDDAHV_2) U30.AD16(VDDAHV_3) U30.AD18(VDDAHV_4) U30.AD20(VDDAHV_5) U30.AD22(VDDAHV_6)
VDDPLL0: C554.1 C561.1 C581.1 C607.1 C640.1 C687.1 FB18.1 U30.J11(AVDDA7) U30.J14(AVDDA8) U30.J17(AVDDA9) U30.J21(AVDDA10) U30.K8(AVDDA6)
CVDD: C125.2 C126.2 C127.2 C128.1 C129.2 C130.1 C134.2 C135.2 C146.1 C147.1 C148.2 C151.1 C152.2 C154.2 C272.1 C273.1 C274.2 C275.2 C277.1 C278.2 C294.1 C295.2 C297.2 C300.2 C301.2 C308.1 C309.1 C310.1 C311.1 C312.1 C313.1 C499.2 C500.2 C501.1 C502.2 C503.2 C504.2 C509.2 C510.2 C511.2 C512.2 C513.2 C514.2 C517.2 C518.1 C569.1 C570.1 C571.1 C572.1 C577.1 C579.1 C580.1 C586.1 C588.1 C589.1 C590.1 C591.1 C597.1 C599.1 C600.1 C601.1 C602.1 C603.1 C610.1 C611.1 C612.1 C613.1 C614.1 C615.1 C620.1 C621.1 C626.1 C644.1 C653.1 C654.1 C655.1 C656.1 C663.1 C665.1 C666.1 C668.1 C673.1 C674.1 C675.1 C677.1 C678.1 C679.1 C680.1 C688.1 C690.1 C691.1 C692.1 C693.1 C697.1 C698.1 C699.1 C700.1 C701.1 C702.1 C703.1 C706.1 C709.1 C758.2 C759.2 C760.2 C761.2 C762.2 C763.2 C764.1 C765.2 C766.1 C767.2 C776.2 C777.1 C780.2 C785.2 C786.2 C799.1 C800.1 C801.1 U30.AA9(CVDD_7) U30.AA11(CVDD_1) U30.AA13(CVDD_2) U30.AA15(CVDD_3) U30.AA17(CVDD_4) U30.AA19(CVDD_5) U30.AA21(CVDD_6) U30.AB10(CVDD_8) U30.AB12(CVDD_9) U30.AB20(CVDD_10) U30.AB22(CVDD_11) U30.K12(CVDD_12) U30.K14(CVDD_13) U30.K16(CVDD_14) U30.K18(CVDD_15) U30.K20(CVDD_16) U30.K22(CVDD_17) U30.L9(CVDD_24) U30.L11(CVDD_18) U30.L13(CVDD_19) U30.L15(CVDD_20) U30.L17(CVDD_21) U30.L19(CVDD_22) U30.L21(CVDD_23) U30.M14(CVDD_25) U30.M18(CVDD_26) U30.M20(CVDD_27) U30.M22(CVDD_28) U30.N9(CVDD_31) U30.N13(CVDD_29) U30.N17(CVDD_30) U30.P10(CVDD_32) U30.P12(CVDD_33) U30.P14(CVDD_34) U30.P18(CVDD_35) U30.P22(CVDD_36) U30.R11(CVDD_37) U30.R13(CVDD_38) U30.R15(CVDD_39) U30.R17(CVDD_40) U30.R19(CVDD_41) U30.R21(CVDD_42) U30.T12(CVDD_43) U30.T14(CVDD_44) U30.T16(CVDD_45) U30.T18(CVDD_46) U30.T20(CVDD_47) U30.T22(CVDD_48) U30.U11(CVDD_49) U30.U13(CVDD_50) U30.U15(CVDD_51) U30.U17(CVDD_52) U30.U19(CVDD_53) U30.U21(CVDD_54) U30.V12(CVDD_55) U30.V14(CVDD_56) U30.V16(CVDD_57) U30.V18(CVDD_58) U30.V20(CVDD_59) U30.V22(CVDD_60) U30.W9(CVDD_66) U30.W11(CVDD_61) U30.W13(CVDD_62) U30.W17(CVDD_63) U30.W19(CVDD_64) U30.W21(CVDD_65) U30.Y10(CVDD_67) U30.Y12(CVDD_68) U30.Y18(CVDD_69) U30.Y20(CVDD_70) U30.Y22(CVDD_71) ; also on sheet 3 35 37
CVDD1: C109.1 C489.1 C555.1 C557.1 C563.1 C576.1 C587.1 C598.1 C623.1 C627.1 C628.1 C637.1 C641.1 C664.1 C676.1 C689.1 C694.1 C704.1 C708.1 U30.AC21(VNWA3) U30.L7(VNWA1) U30.L23(VNWA2) U30.M10(CVDD1_1) U30.M12(CVDD1_2) U30.M16(CVDD1_3) U30.N11(CVDD1_4) U30.N15(CVDD1_5) U30.N19(CVDD1_6) U30.N21(CVDD1_7) U30.P16(CVDD1_8) U30.P20(CVDD1_9) U30.W15(CVDD1_10) U30.Y8(VNWA4) U30.Y14(CVDD1_11) U30.Y16(CVDD1_12) ; also on sheet 34 37
VPP: U30.AF6(VPP)
VPP1V8: C182.1 U30.AF8(VPP2) ; also on sheet 25 37

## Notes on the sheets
sheet 36
- K2L CVVD, CVVD1, bypass caps, K2L 1v8, K2L 1v0 PLL, caps, filters
- Place near to SOC pins
- 0201
- 1206, 0805, 0603
- Place near to SOC pins
- Place near to SOC pins
- Place near to SOC
- Place near to SOC pins
- Place near to SOC pins
- 0402
- Place TOP Tie
- These decaps are added
  recently
- Close to SOC
- Close to SOC
- Close to SOC
- Place near to SOC pins
- Place near to SOC
- Close to SOC
- Place near to SOC pins
- Close to SOC
- Close to SOC
- Place near to SOC pins
- Close to SOC
- Replaced Cap with FB
